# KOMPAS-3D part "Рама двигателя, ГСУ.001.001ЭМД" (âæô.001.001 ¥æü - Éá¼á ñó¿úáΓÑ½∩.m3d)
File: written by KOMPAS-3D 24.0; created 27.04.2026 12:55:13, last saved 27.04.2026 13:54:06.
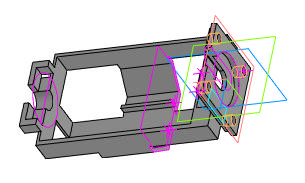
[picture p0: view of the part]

Document properties: Автор: USG_411; Полное имя файла: C:\Users\USG_411.STUD\Desktop\ГМ2704_411-23\Двигатель мясорубки\ГСУ.001.001 ЭСБ - Рама двигателя.m3d

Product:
- Part/product: Рама двигателя  | designation ГСУ.001.001ЭМД
    Масса: 0.2349

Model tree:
1. Эскиз:1
2. Элемент выдавливания:1
     Расстояние 1 = 3
3. Эскиз:2  (with: Грань.Элемент выдавливания:1, Ребро.Элемент выдавливания:1)
4. Элемент выдавливания:2
     Расстояние 1 = 2.5
5. Эскиз:3  (with: Грань.Элемент выдавливания:2, Ребро.Элемент выдавливания:1)
6. Элемент выдавливания:3
     Расстояние 1 = 113
7. Эскиз:4  (with: Грань.Элемент выдавливания:3, Ребро.Элемент выдавливания:3, Вершина.Элемент выдавливания:3)
8. Элемент выдавливания:4
9. Зеркальный массив:1
10. Экземпляр ( 1 )
11. Экземпляр ( 2 )  (with: Элемент выдавливания:4)
12. Эскиз:5  (with: Грань.Элемент выдавливания:3, Ребро.Элемент выдавливания:3)
13. Элемент выдавливания:5
     Расстояние 2 = 9.5
14. Эскиз:6  (with: Грань.Элемент выдавливания:3, Ребро.Элемент выдавливания:4, Вершина.Элемент выдавливания:5, Ребро.Элемент выдавливания:5)
15. Элемент выдавливания:6
     Расстояние 2 = 25
16. Зеркальный массив:2  (with: Экземпляр ( 1 ), Экземпляр ( 2 ), Элемент выдавливания:6)
17. Эскиз:7  (with: Грань.Элемент выдавливания:3, Вершина.Элемент выдавливания:6, Ребро.Элемент выдавливания:4, Ребро.Элемент выдавливания:6)
18. Элемент выдавливания:7
     Расстояние 2 = 25
19. Зеркальный массив:3  (with: Экземпляр ( 1 ), Экземпляр ( 2 ), Элемент выдавливания:7)
20. Эскиз:8  (with: Грань.Элемент выдавливания:7, Вершина.Элемент выдавливания:7, Ребро.Элемент выдавливания:7)
21. Элемент выдавливания:8
     Расстояние 2 = 10
22. Смещенная плоскость:1  (with: Грань.Элемент выдавливания:5)
     Расстояние = 1.5
23. Эскиз:9  (with: Ребро.Элемент выдавливания:5)  (labels: Ребро.Элемент выдавливания:6.Экземпляр ( 2 ))
24. Элемент выдавливания:9
     Расстояние 2 = 30.5
25. Эскиз:10  (with: Грань.Элемент выдавливания:6, Ребро.Элемент выдавливания:3, Ребро.Элемент выдавливания:5)
26. Элемент выдавливания:10  (with: Грань.Элемент выдавливания:9)
     Расстояние 1 = 30.5
27. Эскиз:11  (with: Грань.Элемент выдавливания:6, Ребро.Элемент выдавливания:6, Ребро.Элемент выдавливания:9, Ребро.Элемент выдавливания:10)  (labels: Ребро.Элемент выдавливания:6.Экземпляр ( 2 ))
28. Элемент выдавливания:11  (with: Грань.Элемент выдавливания:7)
29. Массив по сетке:1  (with: Элемент выдавливания:10, Эскиз:10, Ребро.Элемент выдавливания:4)  (2 pattern instances)
     Шаг 1 = 63; Угол раствора = 90
30. Элемент выдавливания:12  (with: Грань.Элемент выдавливания:11)
     Расстояние 2 = 30.5
31. Эскиз:12  (with: Грань.Элемент выдавливания:1, Ребро.Элемент выдавливания:1)
32. Элемент выдавливания:14
     Расстояние 2 = 3
33. Элемент выдавливания:15
     Расстояние 2 = 5.5
34. Эскиз:13  (with: Грань.Элемент выдавливания:1, Ребро.Элемент выдавливания:1)
35. Отверстие:1  (with: Ребро.Элемент выдавливания:15, Ребро.Элемент выдавливания:1)  (labels: M6)
     Глубина выреза = 5.5; Диаметр отверстия = 4.91747; Угол конуса дна = 118; Расстояние 1 = 22; Расстояние 2 = 38
36. M6  (with: Грань.Отверстие:1, Грань.Элемент выдавливания:1, Грань.Элемент выдавливания:5)  (labels: M6; cil0_24705-2004 coarse)
     Длина резьбы = 5.5; Шаг резьбы = 1; Номинальный диаметр резьбы = 6
37. Массив по сетке:2  (with: Отверстие:1, Эскиз:13)  (labels: M6)  (2 pattern instances)
38. Отверстие:1  (with: Эскиз:13)  (labels: M6)
39. Отверстие:1  (with: Эскиз:13)  (labels: M6)
40. Эскиз:14  (with: Вершина.Элемент выдавливания:7)  (labels: Грань.Элемент выдавливания:7.Экземпляр ( 2 ); Вершина.Элемент выдавливания:7.Экземпляр ( 2 ))
41. Элемент выдавливания:16
     Расстояние 2 = 1.5
42. Эскиз:15  (labels: Грань.Элемент выдавливания:7.Экземпляр ( 2 ))
43. Элемент выдавливания:17
     Расстояние 1 = 8.5
44. Эскиз:16  (with: Грань.Элемент выдавливания:17)
45. Элемент выдавливания:19
     Расстояние 2 = 10
46. Эскиз:17  (with: Грань.Элемент выдавливания:17, Ребро.Элемент выдавливания:2, Ребро.Элемент выдавливания:1)
47. Элемент выдавливания:20
     Расстояние 2 = 10
48. Эскиз:18  (with: Грань.Элемент выдавливания:17, Вершина.Элемент выдавливания:19, Ребро.Элемент выдавливания:20)
49. Элемент выдавливания:21
     Расстояние 2 = 10
50. Эскиз:19  (with: Грань.Элемент выдавливания:20, Ребро.Элемент выдавливания:20)
51. Элемент выдавливания:22  (with: Грань.Элемент выдавливания:3)
     Расстояние 2 = 7
52. Эскиз:20  (with: Грань.Элемент выдавливания:3, Ребро.Элемент выдавливания:15, Ребро.Элемент выдавливания:10)
53. Элемент выдавливания:23
54. Эскиз:21  (with: Грань.Элемент выдавливания:9, Ребро.Элемент выдавливания:15, Вершина.Элемент выдавливания:14, Ребро.Элемент выдавливания:23)
55. Элемент выдавливания:24
     Расстояние 2 = 10

Expressions: 44+8+8; 13+5
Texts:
  ГСУ.001.001
  ГСУ.001.001 ЭМД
